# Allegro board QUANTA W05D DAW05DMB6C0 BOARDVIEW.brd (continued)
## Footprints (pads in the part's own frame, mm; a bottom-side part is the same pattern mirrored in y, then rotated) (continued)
BSH-030-01-L-D-A-TR-60P-LDH
  round 1.016 hole 1.016 unplated: (-10.063,-2.666) (10.063,-2.666)
  rect 0.279x2.261 smd: 1(-7.25,-2.864) 2(-6.75,-2.864) 3(-6.25,-2.864) 4(-5.75,-2.864) 5(-5.25,-2.864) 6(-4.75,-2.864) 7(-4.25,-2.864) 8(-3.75,-2.864) 9(-3.25,-2.864) 10(-2.75,-2.864) 11(-2.25,-2.864) 12(-1.75,-2.864) 13(-1.25,-2.864) 14(-0.75,-2.864) 15(-0.25,-2.864) 16(0.25,-2.864) 17(0.75,-2.864) 18(1.25,-2.864) 19(1.75,-2.864) 20(2.25,-2.864) 21(2.75,-2.864) 22(3.25,-2.864) 23(3.75,-2.864) 24(4.25,-2.864) 25(4.75,-2.864) 26(5.25,-2.864) 27(5.75,-2.864) 28(6.25,-2.864) 29(6.75,-2.864) 30(7.25,-2.864) 31(7.25,2.864) 32(6.75,2.864) 33(6.25,2.864) 34(5.75,2.864) 35(5.25,2.864) 36(4.75,2.864) 37(4.25,2.864) 38(3.75,2.864) 39(3.25,2.864) 40(2.75,2.864) 41(2.25,2.864) 42(1.75,2.864) 43(1.25,2.864) 44(0.75,2.864) 45(0.25,2.864) 46(-0.25,2.864) 47(-0.75,2.864) 48(-1.25,2.864) 49(-1.75,2.864) 50(-2.25,2.864) 51(-2.75,2.864) 52(-3.25,2.864) 53(-3.75,2.864) 54(-4.25,2.864) 55(-4.75,2.864) 56(-5.25,2.864) 57(-5.75,2.864) 58(-6.25,2.864) 59(-6.75,2.864) 60(-7.25,2.864)
CC0201_S
  rect 0.254x0.356 smd: 1(0.24,0) 2(-0.24,0)
CC0402
  custom 0.12x0.12 smd: 1(0.39,0) 2(-0.39,0)
CC0603
  rect 0.813x0.711 smd: 1(0.737,0) 2(-0.737,0)
CC0805
  rect 0.94x1.346 smd: 1(0.895,0) 2(-0.895,0)
CC3528
  rect 2.032x2.413 smd: 1(1.6,0) 2(-1.6,0)
CC7343-2_15H
  rect 2.057x2.896 smd: 1(-3.075,0) 2(3.075,0)
CHOKE-ETQP4LR36AFM
  rect 2.794x2.591 smd: 1(-3.2,0) 2(3.2,0)
CHOKE-MPL73-1R5
  rect 1.676x3.404 smd: 1(-2.843,0) 2(2.843,0)
CHOKE-WCM2012-4P
  rect 0.889x0.406 smd: 1(-0.85,0.4) 2(0.85,0.4) 3(0.85,-0.4) 4(-0.85,-0.4)
D-DO-214AC
  rect 1.88x2.032 smd: 1(-2.1,0) 2(2.1,0)
D-SOT523_213-1_6-1
  rect 0.406x0.508 smd: 1(0.5,-0.65) 2(-0.5,-0.65) 3(0,0.65)
DDR-DDRRK-20401-TP4B-204P-RUV
  round 1.092 hole 1.092 unplated: (-33.4,0)
  round 1.6 hole 1.6 unplated: (33.4,0)
  rect 0.356x2.007 smd: 1(31.65,4.1) 2(31.35,-4.1) 3(31.05,4.1) 4(30.75,-4.1) 5(30.45,4.1) 6(30.15,-4.1) 7(29.85,4.1) 8(29.55,-4.1) 9(29.25,4.1) 10(28.95,-4.1) 11(28.65,4.1) 12(28.35,-4.1) 13(28.05,4.1) 14(27.75,-4.1) 15(27.45,4.1) 16(27.15,-4.1) 17(26.85,4.1) 18(26.55,-4.1) 19(26.25,4.1) 20(25.95,-4.1) 21(25.65,4.1) 22(25.35,-4.1) 23(25.05,4.1) 24(24.75,-4.1) 25(24.45,4.1) 26(24.15,-4.1) 27(23.85,4.1) 28(23.55,-4.1) 29(23.25,4.1) 30(22.95,-4.1) 31(22.65,4.1) 32(22.35,-4.1) 33(22.05,4.1) 34(21.75,-4.1) 35(21.45,4.1) 36(21.15,-4.1) 37(20.85,4.1) 38(20.55,-4.1) 39(20.25,4.1) 40(19.95,-4.1) 41(19.65,4.1) 42(19.35,-4.1) 43(19.05,4.1) 44(18.75,-4.1) 45(18.45,4.1) 46(18.15,-4.1) 47(17.85,4.1) 48(17.55,-4.1) 49(17.25,4.1) 50(16.95,-4.1) 51(16.65,4.1) 52(16.35,-4.1) 53(16.05,4.1) 54(15.75,-4.1) 55(15.45,4.1) 56(15.15,-4.1) 57(14.85,4.1) 58(14.55,-4.1) 59(14.25,4.1) 60(13.95,-4.1) 61(13.65,4.1) 62(13.35,-4.1) 63(13.05,4.1) 64(12.75,-4.1) 65(12.45,4.1) 66(12.15,-4.1) 67(11.85,4.1) 68(11.55,-4.1) 69(11.25,4.1) 70(10.95,-4.1) 71(10.65,4.1) 72(10.35,-4.1) 73(7.65,4.1) 74(7.35,-4.1) 75(7.05,4.1) 76(6.75,-4.1) 77(6.45,4.1) 78(6.15,-4.1) 79(5.85,4.1) 80(5.55,-4.1) 81(5.25,4.1) 82(4.95,-4.1) 83(4.65,4.1) 84(4.35,-4.1) 85(4.05,4.1) 86(3.75,-4.1) 87(3.45,4.1) 88(3.15,-4.1) 89(2.85,4.1) 90(2.55,-4.1) 91(2.25,4.1) 92(1.95,-4.1) 93(1.65,4.1) 94(1.35,-4.1) 95(1.05,4.1) 96(0.75,-4.1) 97(0.45,4.1) 98(0.15,-4.1) 99(-0.15,4.1) 100(-0.45,-4.1) 101(-0.75,4.1) 102(-1.05,-4.1) 103(-1.35,4.1) 104(-1.65,-4.1) 105(-1.95,4.1) 106(-2.25,-4.1) 107(-2.55,4.1) 108(-2.85,-4.1) 109(-3.15,4.1) 110(-3.45,-4.1) 111(-3.75,4.1) 112(-4.05,-4.1) 113(-4.35,4.1) 114(-4.65,-4.1) 115(-4.95,4.1) 116(-5.25,-4.1) 117(-5.55,4.1) 118(-5.85,-4.1) 119(-6.15,4.1) 120(-6.45,-4.1) 121(-6.75,4.1) 122(-7.05,-4.1) 123(-7.35,4.1) 124(-7.65,-4.1) 125(-7.95,4.1) 126(-8.25,-4.1) 127(-8.55,4.1) 128(-8.85,-4.1) 129(-9.15,4.1) 130(-9.45,-4.1) 131(-9.75,4.1) 132(-10.05,-4.1) 133(-10.35,4.1) 134(-10.65,-4.1) 135(-10.95,4.1) 136(-11.25,-4.1) 137(-11.55,4.1) 138(-11.85,-4.1) 139(-12.15,4.1) 140(-12.45,-4.1) 141(-12.75,4.1) 142(-13.05,-4.1) 143(-13.35,4.1) 144(-13.65,-4.1) 145(-13.95,4.1) 146(-14.25,-4.1) 147(-14.55,4.1) 148(-14.85,-4.1) 149(-15.15,4.1) 150(-15.45,-4.1) 151(-15.75,4.1) 152(-16.05,-4.1) 153(-16.35,4.1) 154(-16.65,-4.1) 155(-16.95,4.1) 156(-17.25,-4.1) 157(-17.55,4.1) 158(-17.85,-4.1) 159(-18.15,4.1) 160(-18.45,-4.1) 161(-18.75,4.1) 162(-19.05,-4.1) 163(-19.35,4.1) 164(-19.65,-4.1) 165(-19.95,4.1) 166(-20.25,-4.1) 167(-20.55,4.1) 168(-20.85,-4.1) 169(-21.15,4.1) 170(-21.45,-4.1) 171(-21.75,4.1) 172(-22.05,-4.1) 173(-22.35,4.1) 174(-22.65,-4.1) 175(-22.95,4.1) 176(-23.25,-4.1) 177(-23.55,4.1) 178(-23.85,-4.1) 179(-24.15,4.1) 180(-24.45,-4.1) 181(-24.75,4.1) 182(-25.05,-4.1) 183(-25.35,4.1) 184(-25.65,-4.1) 185(-25.95,4.1) 186(-26.25,-4.1) 187(-26.55,4.1) 188(-26.85,-4.1) 189(-27.15,4.1) 190(-27.45,-4.1) 191(-27.75,4.1) 192(-28.05,-4.1) 193(-28.35,4.1) 194(-28.65,-4.1) 195(-28.95,4.1) 196(-29.25,-4.1) 197(-29.55,4.1) 198(-29.85,-4.1) 199(-30.15,4.1) 200(-30.45,-4.1) 201(-30.75,4.1) 202(-31.05,-4.1) 203(-31.35,4.1) 204(-31.65,-4.1)
  rect 4.496x4.597 smd: 207(32.55,12) 208(-32.55,12)
DSM
  rect 0.508x1.016 smd: 1(0,-1.3) 2(0,1.321)
F3_2X1_65-2_8
  rect 0.991x1.803 smd: 1(-1.4,0) 2(1.4,0)
FH35C-31S-0_3SHW-31P-LDH
  rect 0.305x0.787 smd: 1(-4.5,-1.475) 2(-3.9,-1.475) 3(-3.3,-1.475) 4(-2.7,-1.475) 5(-2.1,-1.475) 6(-1.5,-1.475) 7(-0.9,-1.475) 8(-0.3,-1.475) 9(0.3,-1.475) 10(0.9,-1.475) 11(1.5,-1.475) 12(2.1,-1.475) 13(2.7,-1.475) 14(3.3,-1.475) 15(3.9,-1.475) 16(4.5,-1.475)
  rect 0.305x0.66 smd: 17(4.2,1.4) 18(3.6,1.4) 19(3,1.4) 20(2.4,1.4) 21(1.8,1.4) 22(1.2,1.4) 23(0.6,1.4) 24(0,1.4) 25(-0.6,1.4) 26(-1.2,1.4) 27(-1.8,1.4) 28(-2.4,1.4) 29(-3,1.4) 30(-3.6,1.4) 31(-4.2,1.4)
  rect 0.406x0.94 smd: 32(-5.2,-1.2) 33(5.2,-1.2)
GS12407-11141-9H-40P-R
  rect 0.254x1.295 smd: 1(9.75,1.995) 2(9.25,1.995) 3(8.75,1.995) 4(8.25,1.995) 5(7.75,1.995) 6(7.25,1.995) 7(6.75,1.995) 8(6.25,1.995) 9(5.75,1.995) 10(5.25,1.995) 11(4.75,1.995) 12(4.25,1.995) 13(3.75,1.995) 14(3.25,1.995) 15(2.75,1.995) 16(2.25,1.995) 17(1.75,1.995) 18(1.25,1.995) 19(0.75,1.995) 20(0.25,1.995) 21(-0.25,1.995) 22(-0.75,1.995) 23(-1.25,1.995) 24(-1.75,1.995) 25(-2.25,1.995) 26(-2.75,1.995) 27(-3.25,1.995) 28(-3.75,1.995) 29(-4.25,1.995) 30(-4.75,1.995) 31(-5.25,1.995) 32(-5.75,1.995) 33(-6.25,1.995) 34(-6.75,1.995) 35(-7.25,1.995) 36(-7.75,1.995) 37(-8.25,1.995) 38(-8.75,1.995) 39(-9.25,1.995) 40(-9.75,1.995)
  rect 2.261x1.295 smd: 41(8.9,-1.905) 42(0,-1.905) 43(-8.9,-1.905)
  rect 1.194x3.2 smd: 44(12.15,0) 45(-12.15,0)
H-C91D91N
  round 2.311 hole 2.311 unplated: (0,0)
H-TC236IC142BC142D142P2
  round 3.607 hole 3.607: 1(0,0)
H-TE315X354BC138D138P2
  round 3.505 hole 3.505: 1(0,0)
H-TE354X299BC91D91P2
  round 2.311 hole 2.311: 1(0,0)
H-TE354X339BC91D91P2
  round 2.311 hole 2.311: 1(0,0)
H-TE354X339BC138D138P2
  round 3.505 hole 3.505: 1(0,0)
H-TE354X366BC138D138P2
  round 3.505 hole 3.505: 1(0,0)
H-TE413X295BC142D142P2
  round 3.607 hole 3.607: 1(0,0)
H-TE473X378BC138D138P2
  round 3.505 hole 3.505: 1(0,0)
L3_2X2_5-1_55
  rect 1.245x2.007 smd: 1(-1.275,0) 2(1.275,0)
LGA14-5X3-8
  rect 0.61x1.397 smd: 1(2,1.3) 2(1.2,1.3) 3(0.4,1.3) 4(-0.4,1.3) 5(-1.2,1.3) 6(-2,1.3) 8(-2,-1.3) 9(-1.2,-1.3) 10(-0.4,-1.3) 11(0.4,-1.3) 12(1.2,-1.3) 13(2,-1.3)
  rect 1.702x0.635 smd: 7(-2.15,0) 14(2.15,0)
LGA16-4X4-65
  rect 0.991x0.381 smd: 1(-2,0.975) 2(-2,0.325) 3(-2,-0.325) 4(-2,-0.975) 9(2,-0.975) 10(2,-0.325) 11(2,0.325) 12(2,0.975)
  rect 0.381x0.991 smd: 5(-0.975,-2) 6(-0.325,-2) 7(0.325,-2) 8(0.975,-2) 13(0.975,2) 14(0.325,2) 15(-0.325,2) 16(-0.975,2)
LQFP64-12X12-5-STM32F405RGT6TR
  rect 1.194x0.305 smd: 1(-5.75,3.75) 2(-5.75,3.25) 3(-5.75,2.75) 4(-5.75,2.25) 5(-5.75,1.75) 6(-5.75,1.25) 7(-5.75,0.75) 8(-5.75,0.25) 9(-5.75,-0.25) 10(-5.75,-0.75) 11(-5.75,-1.25) 12(-5.75,-1.75) 13(-5.75,-2.25) 14(-5.75,-2.75) 15(-5.75,-3.25) 16(-5.75,-3.75) 33(5.75,-3.75) 34(5.75,-3.25) 35(5.75,-2.75) 36(5.75,-2.25) 37(5.75,-1.75) 38(5.75,-1.25) 39(5.75,-0.75) 40(5.75,-0.25) 41(5.75,0.25) 42(5.75,0.75) 43(5.75,1.25) 44(5.75,1.75) 45(5.75,2.25) 46(5.75,2.75) 47(5.75,3.25) 48(5.75,3.75)
  rect 0.305x1.194 smd: 17(-3.75,-5.75) 18(-3.25,-5.75) 19(-2.75,-5.75) 20(-2.25,-5.75) 21(-1.75,-5.75) 22(-1.25,-5.75) 23(-0.75,-5.75) 24(-0.25,-5.75) 25(0.25,-5.75) 26(0.75,-5.75) 27(1.25,-5.75) 28(1.75,-5.75) 29(2.25,-5.75) 30(2.75,-5.75) 31(3.25,-5.75) 32(3.75,-5.75) 49(3.75,5.75) 50(3.25,5.75) 51(2.75,5.75) 52(2.25,5.75) 53(1.75,5.75) 54(1.25,5.75) 55(0.75,5.75) 56(0.25,5.75) 57(-0.25,5.75) 58(-0.75,5.75) 59(-1.25,5.75) 60(-1.75,5.75) 61(-2.25,5.75) 62(-2.75,5.75) 63(-3.25,5.75) 64(-3.75,5.75)
LQFP128-16X16-4
  rect 0.203x1.499 smd: 1(-6.2,-7.85) 2(-5.8,-7.85) 3(-5.4,-7.85) 4(-5,-7.85) 5(-4.6,-7.85) 6(-4.2,-7.85) 7(-3.8,-7.85) 8(-3.4,-7.85) 9(-3,-7.85) 10(-2.6,-7.85) 11(-2.2,-7.85) 12(-1.8,-7.85) 13(-1.4,-7.85) 14(-1,-7.85) 15(-0.6,-7.85) 16(-0.2,-7.85) 17(0.2,-7.85) 18(0.6,-7.85) 19(1,-7.85) 20(1.4,-7.85) 21(1.8,-7.85) 22(2.2,-7.85) 23(2.6,-7.85) 24(3,-7.85) 25(3.4,-7.85) 26(3.8,-7.85) 27(4.2,-7.85) 28(4.6,-7.85) 29(5,-7.85) 30(5.4,-7.85) 31(5.8,-7.85) 32(6.2,-7.85) 65(6.2,7.85) 66(5.8,7.85) 67(5.4,7.85) 68(5,7.85) 69(4.6,7.85) 70(4.2,7.85) 71(3.8,7.85) 72(3.4,7.85) 73(3,7.85) 74(2.6,7.85) 75(2.2,7.85) 76(1.8,7.85) 77(1.4,7.85) 78(1,7.85) 79(0.6,7.85) 80(0.2,7.85) 81(-0.2,7.85) 82(-0.6,7.85) 83(-1,7.85) 84(-1.4,7.85) 85(-1.8,7.85) 86(-2.2,7.85) 87(-2.6,7.85) 88(-3,7.85) 89(-3.4,7.85) 90(-3.8,7.85) 91(-4.2,7.85) 92(-4.6,7.85) 93(-5,7.85) 94(-5.4,7.85) 95(-5.8,7.85) 96(-6.2,7.85)
  rect 1.499x0.203 smd: 33(7.85,-6.2) 34(7.85,-5.8) 35(7.85,-5.4) 36(7.85,-5) 37(7.85,-4.6) 38(7.85,-4.2) 39(7.85,-3.8) 40(7.85,-3.4) 41(7.85,-3) 42(7.85,-2.6) 43(7.85,-2.2) 44(7.85,-1.8) 45(7.85,-1.4) 46(7.85,-1) 47(7.85,-0.6) 48(7.85,-0.2) 49(7.85,0.2) 50(7.85,0.6) 51(7.85,1) 52(7.85,1.4) 53(7.85,1.8) 54(7.85,2.2) 55(7.85,2.6) 56(7.85,3) 57(7.85,3.4) 58(7.85,3.8) 59(7.85,4.2) 60(7.85,4.6) 61(7.85,5) 62(7.85,5.4) 63(7.85,5.8) 64(7.85,6.2) 97(-7.85,6.2) 98(-7.85,5.8) 99(-7.85,5.4) 100(-7.85,5) 101(-7.85,4.6) 102(-7.85,4.2) 103(-7.85,3.8) 104(-7.85,3.4) 105(-7.85,3) 106(-7.85,2.6) 107(-7.85,2.2) 108(-7.85,1.8) 109(-7.85,1.4) 110(-7.85,1) 111(-7.85,0.6) 112(-7.85,0.2) 113(-7.85,-0.2) 114(-7.85,-0.6) 115(-7.85,-1) 116(-7.85,-1.4) 117(-7.85,-1.8) 118(-7.85,-2.2) 119(-7.85,-2.6) 120(-7.85,-3) 121(-7.85,-3.4) 122(-7.85,-3.8) 123(-7.85,-4.2) 124(-7.85,-4.6) 125(-7.85,-5) 126(-7.85,-5.4) 127(-7.85,-5.8) 128(-7.85,-6.2)
MINIPCI-MPCET-SSC10-TS10-52P
  rect 0.61x1.295 smd: 1(11.8,8.15) 3(11,8.15) 5(10.2,8.15) 7(9.4,8.15) 9(8.6,8.15) 11(7.8,8.15) 13(7,8.15) 15(6.2,8.15) 17(2.2,8.15) 19(1.4,8.15) 21(0.6,8.15) 23(-0.2,8.15) 25(-1,8.15) 27(-1.8,8.15) 29(-2.6,8.15) 31(-3.4,8.15) 33(-4.2,8.15) 35(-5,8.15) 37(-5.8,8.15) 39(-6.6,8.15) 41(-7.4,8.15) 43(-8.2,8.15) 45(-9,8.15) 47(-9.8,8.15) 49(-10.6,8.15) 51(-11.4,8.15)
  oval 0.61x0.889 hole 0.381x0.61: 2(11.4,6.65) 4(10.6,6.65) 6(9.8,6.65) 8(9,6.65) 10(8.2,6.65) 12(7.4,6.65) 14(6.6,6.65) 16(5.8,6.65) 18(1.8,6.65) 20(1,6.65) 22(0.2,6.65) 24(-0.6,6.65) 26(-1.4,6.65) 28(-2.2,6.65) 30(-3,6.65) 32(-3.8,6.65) 34(-4.6,6.65) 36(-5.4,6.65) 38(-6.2,6.65) 40(-7,6.65) 42(-7.8,6.65) 44(-8.6,6.65) 46(-9.4,6.65) 48(-10.2,6.65) 50(-11,6.65) 52(-11.8,6.65)
  oval 0.787x2.388 hole 0.406x2.007: 53(14.35,0) 54(-14.35,0)
ML1220-SMT
  round 0.711 hole 0.711 unplated: (0,-3.988)
  round 1.092 hole 1.092 unplated: (0,3.988)
  rect 2.997x1.499 smd: 1(-7.391,0) 2(7.391,0)
MSOP8-4_9-65
  rect 0.406x1.448 smd: 1(-0.975,-2.325) 2(-0.325,-2.325) 3(0.325,-2.325) 4(0.975,-2.325) 5(0.975,2.325) 6(0.325,2.325) 7(-0.325,2.325) 8(-0.975,2.325)
PG-TSDSON-8-8P-R
  rect 0.33x0.787 smd: 1(0.975,1.5) 2(0.325,1.5) 3(-0.325,1.5) 4(-0.975,1.5)
  custom 0.573x0.573 smd: 5(0,-0.72)
  rect 0.33x0.66 smd: 6(-0.325,-1.575) 7(0.325,-1.575) 8(0.975,-1.575)
POWER-5X6-1_27-7P
  rect 0.66x0.635 smd: 1(-1.905,-2.835) 5(1.905,2.835) 6(0.635,2.835) 7(-0.635,2.835) 8(-1.905,2.835)
  custom 0.485x0.485 smd: 2(0.115,-2.18)
  rect 3.988x2.159 smd: 9(0,0.525)
PVQFN20-3_5X3_5-5-25P
  rect 0.279x0.838 smd: 1(-1,-1.725) 2(-0.5,-1.725) 3(0,-1.725) 4(0.5,-1.725) 5(1,-1.725) 11(1,1.725) 12(0.5,1.725) 13(0,1.725) 14(-0.5,1.725) 15(-1,1.725)
  rect 0.838x0.279 smd: 6(1.725,-1) 7(1.725,-0.5) 8(1.725,0) 9(1.725,0.5) 10(1.725,1) 16(-1.725,1) 17(-1.725,0.5) 18(-1.725,0) 19(-1.725,-0.5) 20(-1.725,-1)
  rect 2.057x2.057 smd: 21(0,0)
  round 0.61 hole 0.305: 22(-0.5,-0.5) 23(0.5,-0.5) 24(0.5,0.5) 25(-0.5,0.5)
PVQFN24-4X4-5-34P
  rect 0.279x0.838 smd: 1(1.25,1.975) 2(0.75,1.975) 3(0.25,1.975) 4(-0.25,1.975) 5(-0.75,1.975) 6(-1.25,1.975) 13(-1.25,-1.975) 14(-0.75,-1.975) 15(-0.25,-1.975) 16(0.25,-1.975) 17(0.75,-1.975) 18(1.25,-1.975)
  rect 0.838x0.279 smd: 7(-1.975,1.25) 8(-1.975,0.75) 9(-1.975,0.25) 10(-1.975,-0.25) 11(-1.975,-0.75) 12(-1.975,-1.25) 19(1.975,-1.25) 20(1.975,-0.75) 21(1.975,-0.25) 22(1.975,0.25) 23(1.975,0.75) 24(1.975,1.25)
  rect 2.438x2.438 smd: 25(0,0)
  round 0.61 hole 0.305: 26(-0.75,0.75) 27(0,0.75) 28(0.75,0.75) 29(-0.75,0) 30(0,0) 31(0.75,0) 32(-0.75,-0.75) 33(0,-0.75) 34(0.75,-0.75)
PWQFN20-4X4-5-30P
  rect 0.279x0.838 smd: 1(1,1.975) 2(0.5,1.975) 3(0,1.975) 4(-0.5,1.975) 5(-1,1.975) 11(-1,-1.975) 12(-0.5,-1.975) 13(0,-1.975) 14(0.5,-1.975) 15(1,-1.975)
  rect 0.838x0.279 smd: 6(-1.975,1) 7(-1.975,0.5) 8(-1.975,0) 9(-1.975,-0.5) 10(-1.975,-1) 16(1.975,-1) 17(1.975,-0.5) 18(1.975,0) 19(1.975,0.5) 20(1.975,1)
  rect 2.692x2.692 smd: 21(0,0)
  round 0.61 hole 0.305: 22(-0.9,0.9) 23(0,0.9) 24(0.9,0.9) 25(-0.9,0) 26(0,0) 27(0.9,0) 28(-0.9,-0.9) 29(0,-0.9) 30(0.9,-0.9)
QFN14-3X3-4-16P
  rect 1.092x0.203 smd: 1(-1.25,0.525) 2(-1.25,-0.175) 8(1.25,-0.525) 9(1.25,0.175)
  rect 0.203x0.711 smd: 3(-0.8,-1.45) 4(-0.4,-1.45) 5(0,-1.45) 6(0.4,-1.45) 7(0.8,-1.45) 10(0.8,1.45) 11(0.4,1.45) 12(0,1.45) 13(-0.4,1.45) 14(-0.8,1.45)
  rect 0.66x0.203 smd: 15(0,0.165) 16(0,-0.435)
QFN20-4X4-5-21P-ADG786
  rect 0.279x1.194 smd: 1(-1,-2) 2(-0.5,-2) 3(0,-2) 4(0.5,-2) 5(1,-2) 11(1,2) 12(0.5,2) 13(0,2) 14(-0.5,2) 15(-1,2)
  rect 1.194x0.279 smd: 6(2,-1) 7(2,-0.5) 8(2,0) 9(2,0.5) 10(2,1) 16(-2,1) 17(-2,0.5) 18(-2,0) 19(-2,-0.5) 20(-2,-1)
  rect 2.108x2.108 smd: 21(0,0)
QFN23-4X4-5
  rect 0.457x0.254 smd: 1(-1.825,1.25) 2(-1.825,0.75) 3(-1.825,0.25) 4(-1.825,-0.25) 5(-1.825,-0.75) 6(-1.825,-1.25) 12(1.825,-1.25) 13(1.825,-0.75) 14(1.825,-0.25) 15(1.825,0.25) 16(1.825,0.75) 17(1.825,1.25)
  rect 0.254x0.457 smd: 7(-1.25,-1.825) 8(-0.75,-1.825) 10(0.75,-1.825) 18(1.25,1.825) 19(0.75,1.825) 20(0.25,1.825) 21(-0.25,1.825) 22(-0.75,1.825) 23(-1.25,1.825)
  custom 0.335x0.335 smd: 9(-0.67,-0.335)
  custom 0.249x0.249 smd: 11(0.867,-0.335)
QFN28-4X4-4-29P-NCP81101MNTWG
  rect 0.965x0.203 smd: 1(-2.03,1.2) 2(-2.03,0.8) 3(-2.03,0.4) 4(-2.03,0) 5(-2.03,-0.4) 6(-2.03,-0.8) 7(-2.03,-1.2) 15(2.03,-1.2) 16(2.03,-0.8) 17(2.03,-0.4) 18(2.03,0) 19(2.03,0.4) 20(2.03,0.8) 21(2.03,1.2)
  rect 0.203x0.965 smd: 8(-1.2,-2.03) 9(-0.8,-2.03) 10(-0.4,-2.03) 11(0,-2.03) 12(0.4,-2.03) 13(0.8,-2.03) 14(1.2,-2.03) 22(1.2,2.03) 23(0.8,2.03) 24(0.4,2.03) 25(0,2.03) 26(-0.4,2.03) 27(-0.8,2.03) 28(-1.2,2.03)
  rect 2.718x2.718 smd: 29(0,0)
QFN40-5X5-4-41P-92HD99
  rect 0.203x0.991 smd: 1(-1.8,-2.6) 2(-1.4,-2.6) 3(-1,-2.6) 4(-0.6,-2.6) 5(-0.2,-2.6) 6(0.2,-2.6) 7(0.6,-2.6) 8(1,-2.6) 9(1.4,-2.6) 10(1.8,-2.6) 21(1.8,2.6) 22(1.4,2.6) 23(1,2.6) 24(0.6,2.6) 25(0.2,2.6) 26(-0.2,2.6) 27(-0.6,2.6) 28(-1,2.6) 29(-1.4,2.6) 30(-1.8,2.6)
  rect 0.991x0.203 smd: 11(2.6,-1.8) 12(2.6,-1.4) 13(2.6,-1) 14(2.6,-0.6) 15(2.6,-0.2) 16(2.6,0.2) 17(2.6,0.6) 18(2.6,1) 19(2.6,1.4) 20(2.6,1.8) 31(-2.6,1.8) 32(-2.6,1.4) 33(-2.6,1) 34(-2.6,0.6) 35(-2.6,0.2) 36(-2.6,-0.2) 37(-2.6,-0.6) 38(-2.6,-1) 39(-2.6,-1.4) 40(-2.6,-1.8)
  rect 3.708x3.708 smd: 41(0,0)
RC0201_S
  rect 0.254x0.356 smd: 1(0.24,0) 2(-0.24,0)
RC0402
  custom 0.12x0.12 smd: 1(0.39,0) 2(-0.39,0)
RC0603
  rect 0.813x0.711 smd: 1(0.737,0) 2(-0.737,0)
RC0805
  rect 0.94x1.346 smd: 1(0.895,0) 2(-0.895,0)
SC70-2_1-65-6P
  rect 1.27x0.279 smd: 1(1.02,-0.65) 2(1.02,0) 3(1.02,0.65) 4(-1.02,0.65) 5(-1.02,0) 6(-1.02,-0.65)
SHORT0201
  rect 0.343x0.381 smd: 1(-0.225,0) 2(0.225,0)
SHORT0402
  rect 0.648x0.5 smd: 1(-0.39,0) 2(0.39,0)
SHORT0603
  rect 1.219x0.711 smd: 1(0.737,0) 2(-0.737,0)
SHORT0805
  rect 1.422x1.346 smd: 1(0.895,0) 2(-0.895,0)
SHORT-SOLDERJUMPER-3
  custom 0.508x0.508 smd: 1(-1.016,0)
  custom 0.381x0.381 smd: 2(1.016,0)
SO-8FL-5P
  rect 0.762x0.991 smd: 1(1.905,3.73) 2(0.635,3.73) 3(-0.635,3.73) 4(-1.905,3.73)
  custom 1.132x1.132 smd: 5(0,0)
SOIC8-8-1_27
  rect 0.533x1.6 smd: 1(1.905,3.8) 2(0.635,3.8) 3(-0.635,3.8) 4(-1.905,3.8) 5(-1.905,-3.8) 6(-0.635,-3.8) 7(0.635,-3.8) 8(1.905,-3.8)
SOT23-5
  rect 0.711x1.016 smd: 1(-0.95,-1.2) 2(0,-1.2) 3(0.95,-1.2) 4(0.95,1.2) 5(-0.95,1.2)
SOT23_213-3_3-2
  rect 1.016x1.27 smd: 1(1.016,-1.016) 2(-1.016,-1.016) 3(0,1.016)
SOT353-1-2_125-65-5P
  rect 0.279x1.245 smd: 1(-0.65,-1.045) 2(0,-1.045) 3(0.65,-1.045) 4(0.65,1.045) 5(-0.65,1.045)
SOT363-2_1-65-6P
  rect 0.889x0.356 smd: 1(0.8,-0.65) 2(0.8,0) 3(0.8,0.65) 4(-0.8,0.65) 5(-0.8,0) 6(-0.8,-0.65)
SOT523_213-1_6-1-3P
  rect 0.279x1.118 smd: 1(0.5,-0.84) 2(-0.5,-0.84) 3(0,0.84)
SSOP5-P-A-TOSHIBA-B
  rect 0.305x1.067 smd: 1(0.65,0.85) 2(0,0.85) 3(-0.65,0.85) 4(-0.65,-0.85) 5(0.65,-0.85)
TO252_134-9_9-4_57-SMT
  rect 2.997x1.499 smd: 1(8.1,-2.286) 3(8.1,2.286)
  rect 5.613x6.248 smd: 4(0.6,0)
TP1250-P14_4
  round 0.305 smd: 1(0,0)
TP2050
  round 0.508 smd: 1(0,0)
TP2075
  round 0.508 smd: 1(0,0)
TP2650
  round 0.66 smd: 1(0,0)
TP2675
  round 0.66 smd: 1(0,0)
TQFN20-3X3-4-21P
  rect 0.711x0.203 smd: 1(-1.5,0.8) 2(-1.5,0.4) 3(-1.5,0) 4(-1.5,-0.4) 5(-1.5,-0.8) 11(1.5,-0.8) 12(1.5,-0.4) 13(1.5,0) 14(1.5,0.4) 15(1.5,0.8)
  rect 0.203x0.711 smd: 6(-0.8,-1.5) 7(-0.4,-1.5) 8(0,-1.5) 9(0.4,-1.5) 10(0.8,-1.5) 16(0.8,1.5) 17(0.4,1.5) 18(0,1.5) 19(-0.4,1.5) 20(-0.8,1.5)
  rect 1.499x1.499 smd: 21(0,0)
TSOP6-2_8-95
  rect 0.635x0.787 smd: 1(-0.95,-1.2) 2(0,-1.2) 3(0.95,-1.2) 4(0.95,1.2) 5(0,1.2) 6(-0.95,1.2)
TSSOP28-6_4-65
  rect 0.279x1.499 smd: 1(-4.225,-3.038) 2(-3.575,-3.038) 3(-2.925,-3.038) 4(-2.275,-3.038) 5(-1.625,-3.038) 6(-0.975,-3.038) 7(-0.325,-3.038) 8(0.325,-3.038) 9(0.975,-3.038) 10(1.625,-3.038) 11(2.275,-3.038) 12(2.925,-3.038) 13(3.575,-3.038) 14(4.225,-3.038) 15(4.225,3.038) 16(3.575,3.038) 17(2.925,3.038) 18(2.275,3.038) 19(1.625,3.038) 20(0.975,3.038) 21(0.325,3.038) 22(-0.325,3.038) 23(-0.975,3.038) 24(-1.625,3.038) 25(-2.275,3.038) 26(-2.925,3.038) 27(-3.575,3.038) 28(-4.225,3.038)
UMT_213-3-1_3
  rect 1.016x0.762 smd: 1(0.991,0.66) 2(0.991,-0.66) 3(-0.991,0)
unnamed#2
  round 1.016 smd: 1(0,0)
VQFN14-3_5X3_5-5-15P
  rect 0.838x0.279 smd: 1(-1.725,-0.75) 7(1.725,-0.75) 8(1.725,0.75) 14(-1.725,0.75)
  rect 0.279x0.838 smd: 2(-1,-1.725) 3(-0.5,-1.725) 4(0,-1.725) 5(0.5,-1.725) 6(1,-1.725) 9(1,1.725) 10(0.5,1.725) 11(0,1.725) 12(-0.5,1.725) 13(-1,1.725)
  rect 2.057x2.057 smd: 15(0,0)
XTL-3_2X1_5-2_5-0_8H
  rect 0.991x1.803 smd: 1(-1.25,0) 2(1.25,0)
XTL-3_2X2_5-2_2X1_7-0_8H
  rect 1.397x1.194 smd: 1(-1.1,-0.85) 2(1.1,-0.85) 3(1.1,0.85) 4(-1.1,0.85)
XTL-3_2X2_5-2_2X1_8-4P
  rect 1.397x1.194 smd: 1(-1.1,-0.9) 2(1.1,-0.9) 3(1.1,0.9) 4(-1.1,0.9)

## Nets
51216VBST: PR125.2 PU8.15
51216VBST_S: PC143.1 PR125.1
51216VDDQSNS: PR126.1 PU8.9
81101VCC: PC61.2 PR66.1 PU3.28
81101VRMP: PC64.1 PR64.1 PU3.7
81101VSN: PC47.2 PR37.1 PU3.26
81101VSP: PC60.2 PR45.1 PU3.27
+0.75V_DDR_VTT: C308.1 C313.1 C324.1 C338.1 C339.1 JDIM1.203 JDIM1.204 PC141.1 PU8.1 PU8.3
+1.05V: C50.2 C120.1 C139.1 C162.1 C168.1 C175.1 C176.1 C250.1 C262.2 CN1.9 CN1.52 L6.2 L7.2 L11.2 PC90.1 PC105.1 PJP1.2 PL10.2 PQ5.5 PQ5.6 PQ5.7 PQ5.8 R46.2 R74.2 R75.2 R118.1 R328.1 R350.2 U20.AE8 U20.AE9 U20.AF9 U20.AF22 U20.AG8 U20.AG13 U20.AG14 U20.AG16 U20.AG17 U20.H11 U20.H15 U20.J11 U20.N8 U20.P9
+1.5V: C27.1 C73.1 C167.1 C352.1 C356.1 C359.1 CN5.6 CN5.28 CN5.48 CN14.6 CN14.28 CN14.48 L16.1 PC45.1 PC59.2 PL2.2 PR59.1 R260.2 R431.2 U20.J15
+1.05V_MODPHY: C58.2 C99.2 C100.2 L9.1 L10.1 PC92.1 PC107.1 PL10.1 PQ5.1 PQ5.2 PQ5.3 PR65.1 U20.K9 U20.L10 U20.M9
+1.05V_S2: PC62.1 PC63.1 PC69.1 PC70.1 PC94.1 PJP1.1 PL9.2 PR85.2
+1.05VS5: R329.1 R343.1 R347.1 R350.1 R351.1
+1.8VREF: PC139.1 PR124.1 PU8.6
+1.35VSUS: C299.1 C300.1 C301.1 C302.1 C303.1 C304.1 C305.1 C306.1 C310.1 C315.1 C316.1 C317.1 C318.1 C321.1 C322.1 C325.1 C326.1 C327.1 C328.1 C329.1 C330.1 C331.1 C332.1 C333.1 C334.1 C335.1 C336.1 JDIM1.75 JDIM1.76 JDIM1.81 JDIM1.82 JDIM1.87 JDIM1.88 JDIM1.93 JDIM1.94 JDIM1.99 JDIM1.100 JDIM1.105 JDIM1.106 JDIM1.111 JDIM1.112 JDIM1.117 JDIM1.118 JDIM1.123 JDIM1.124 PC147.1 PJP4.2 PU8.2 Q27.3 R384.1 R455.2 R466.1 U20.AH26 U20.AJ31 U20.AJ33 U20.AJ37 U20.AN33 U20.AP43 U20.AR48 U20.AY35 U20.AY40 U20.AY44 U20.AY50 U22.5
+1.35VSUS_S: PC146.1 PC148.1 PJP4.1 PL14.2 PR126.2
+3.3VS5_S: PC8.1 PC9.1 PC10.1 PC58.1 PC76.1 PC78.1 PJP2.1 PL5.2 PR78.2
+3V: C2.2 C3.2 C4.2 C13.2 C17.2 C38.2 C42.1 C67.2 C72.2 C83.1 C84.1 C94.2 C115.1 C177.2 C181.1 C242.1 C243.1 C277.2 C289.1 C291.2 C295.2 C297.1 C307.1 C314.1 C319.1 C320.1 C346.1 C347.1 C355.1 C357.1 C358.1 C360.1 C362.2 C364.2 C365.2 CN3.1 CN12.1 CN12.2 CN13.15 CN13.16 CN14.2 CN14.24 CN14.39 CN14.41 CN14.52 EC2.1 EC4.1 EC5.1 EC8.1 EC9.1 EC11.1 EC12.1 EC15.1 JDIM1.199 L14.2 L15.2 L17.1 L18.1 PC98.1 PC99.1 PQ10.1 PQ10.2 PQ10.3 PR61.2 PR77.2 Q21.2 Q21.5 Q22.2 Q22.5 R14.2 R18.2 R25.1 R38.1 R47.2 R51.2 R53.2 R56.1 R58.2 R59.1 R65.2 R77.2 R79.2 R86.2 R89.2 R98.1 R99.1 R105.1 R106.1 R113.2 R116.1 R119.1 R128.2 R132.1 R139.1 R151.1 R160.1 R161.1 R177.2 R184.1 R185.1 R187.2 R188.2 R189.2 R190.2 R191.2 R193.1 R194.2 R197.2 R198.2 R199.2 R201.1 R202.2 R203.2 R204.2 R208.2 R209.1 R214.2 R215.2 R216.2 R217.2 R218.2 R219.2 R248.2 R259.2 R269.1 R273.2 R285.2 R286.1 R287.2 R288.2 R290.1 R291.2 R293.2 R294.2 R299.1 R302.2 R304.2 R305.1 R308.2 R310.1 R312.1 R313.2 R314.2 R320.2 R324.2 R337.2 R338.2 R345.2 R346.2 R356.2 R430.2 R451.2 R457.2 R462.1 R469.2 RP1.5 RP1.10 RP2.5 RP2.10 RP3.5 RP3.10 U1.1 U1.14 U3.14 U5.1 U5.13 U5.19 U5.32 U5.48 U5.64 U8.4 U8.5 U10.6 U10.10 U10.16 U10.20 U13.1 U15.10 U15.19 U15.24 U20.K14 U20.K16 U20.T9 U20.U8 U20.V8 U20.W9 U21.1 U23.1 U23.4 U23.5 U23.15 U23.16
+3V_AVDD: C229.2 C231.1 C268.1 C269.1 L15.1 R317.1 R334.2 U14.5 U18.22
+3V_AVDD_2: C227.1 C232.1 L14.1 U18.30
+3V_DEEP_SUS: C109.2 C233.2 C241.2 C249.2 CN2.1 R140.1 R205.2 R264.1 R268.1 R271.2 R300.1 R315.1 R325.2 R326.2 R333.2 R348.2 R349.1 R352.2 R358.2 R363.2 R364.2 R369.1 R370.1 R372.2 R373.2 R374.2 R377.2 R378.1 R379.2 R381.2 R396.2 R400.2 R403.1 R404.2 R406.2 R407.2 R408.2 R412.1 R413.2 R422.2 R425.1 R426.2 R438.2 R448.2 U11.5 U17.1 U20.AA9 U20.AC9 U20.AE20 U20.AE21 U20.AH11
+3V_DVDD: C252.1 C253.1 L18.2 R237.2 U18.9
+3V_DVDD-IO: C236.1 L16.2 L17.2 U18.7
+3V_RTC: C9.1 C290.1 C292.1 C293.1 D1.3 R22.1 R23.1 R410.1 R415.2 R423.1 U20.AG10
+3V_RTC_0: CN4.1 Q1.1 R15.1
+3V_RTC_1: D1.1 R15.2
+3V_WLAN_P: C11.1 C68.1 C92.1 C150.1 C157.1 C366.1 CN5.2 CN5.24 CN5.39 CN5.41 CN5.52 Q7.3 Q12.2 Q13.2 R42.2 R48.1 R51.1 R57.2 R120.2
+3VLCD_CON: C75.1 C88.2 C104.2 C113.1 C122.2 CN7.11 CN7.12 L8.1
+3VPCU: C23.2 C30.1 C31.1 C32.1 C65.1 C69.1 C87.1 C125.1 C179.1 C184.1 C192.1 C195.1 C323.2 CN6.40 CN13.13 D1.2 D3.1 L1.2 PC84.2 PR72.2 PR119.1 PU4.6 R13.1 R16.1 R24.1 R27.1 R33.1 R37.1 R44.1 R50.2 R61.2 R84.1 R100.1 R104.1 R107.1 R125.1 R162.1 R178.1 R179.1 R186.1 R220.1 R221.1 R222.1 R223.1 R224.1 R225.1 R226.1 R477.1 R478.2 R479.1 R480.1 R482.1 R485.1 U4.6 U7.9 U7.22 U7.33 U7.96 U7.111 U7.125
+3VPCU_EC: C12.1 C18.1 L1.1 U7.67
+3VS5: C5.2 C34.1 C118.2 C180.2 C182.1 C244.2 C245.2 C287.1 CN2.7 PC112.2 PJP2.2 PQ10.5 PQ10.6 PQ10.7 PQ10.8 PR49.1 PR84.1 Q7.1 R122.1 R130.1 R133.1 R137.1 R147.1 R149.1 R163.1 R165.1 R192.1 R254.1 R271.1 R360.2 R368.2 R385.2 R389.2 R402.2 R405.2 R428.2 R445.2 U12.1 U12.13 U15.5 U16.5 U17.4 U17.5 U20.AH10
+3VSPI: C152.1 C153.2 R112.2 R140.2 R153.1 R179.2 U9.8
+5V: C44.1 C111.1 C126.2 C156.1 C196.1 C201.1 C207.1 C343.2 C344.1 CN6.8 CN6.9 FAN1.1 L13.2 PC125.1 PC126.1 PQ11.1 PQ11.2 PQ11.3 PR73.1 Q10.2 R41.1 R67.1 R246.1 R252.1 R475.2 R476.2 U6.1 U14.1
+5V_AMP: C217.2 C225.2 L13.1 R330.1 R335.2 U19.12 U19.20
+5V_PVDD: C199.1 C200.1 C216.1 C222.1 R246.2 U18.31 U18.38
+5VALW: PC24.2 PD2.1 PU4.11
+5VPCU: PD2.3 PR25.2 R19.2 R21.1 R471.1
+5VS5: PC17.2 PC18.2 PC123.2 PC142.1 PD2.2 PJP3.2 PQ11.5 PQ11.6 PQ11.7 PQ11.8 PR66.2 PU1.7 PU1.21 PU3.15 PU8.12 R464.1
+5VS5_S: PC95.1 PC106.1 PC108.1 PC109.1 PC110.1 PC111.1 PJP3.1 PL4.2 PR88.2 PU5.7
+12VALW: PC101.1 PU6.13
+V1.05A_AOSCSUS: C286.2 TP34.1 U20.AB8
+V1.05A_SUS_PCH: TP35.1 U20.AD8 U20.AD10
+V1.05A_USB2SUS: TP49.1 U20.AH13
+V1.05A_VCCUSB3SUS: TP18.1 U20.J13
+V1.05S_APLLOPI: C95.1 C124.1 C149.1 L7.1 U20.AA21 U20.W21
+V1.05S_ASATA3PLL: C93.2 C123.2 C135.2 L9.2 R155.1 R169.1 U20.B11
+V1.05S_AUSB3PLL: C116.2 C136.2 C169.2 L10.2 R164.1 R174.2 U20.B18
+V1.05S_AXCK_DCB: C70.1 C71.1 C82.1 L6.1 U20.J18 U20.K19
+V1.05S_AXCK_LCPLL: C117.1 C151.1 C170.1 L11.1 R180.1 U20.A20
+V1.05S_SSCF100: C85.2 R74.1 U20.J17
+V1.05S_SSCFF: C76.2 R75.1 U20.R21 U20.T21
+V1.05S_VCCST: C258.1 C259.1 PC100.2 PR75.1 PR89.1 PR90.1 PR97.1 R32.2 R55.1 R96.2 R114.2 R244.1 R253.1 R258.1 R266.2 R277.1 R328.2 R437.1 U20.AC22 U20.AE22 U20.AE23
+V3.3DX_1.5DX_ADO: C294.1 R430.1 R431.1 U20.AH14
+V3.3M_PSPI: C186.1 R187.1 R205.1 U20.Y8
+VCC_CORE: C20.1 C21.1 C35.1 C46.1 C47.1 C48.1 C49.1 C59.1 C60.1 C61.1 C62.1 C63.1 C77.1 C78.1 C79.1 C80.1 C81.1 C103.1 C105.1 C106.1 C107.1 C108.1 C127.1 C129.1 C130.1 C131.1 C132.1 C164.1 C165.1 C166.1 EC1.1 EC3.1 EC6.1 EC7.1 PC32.1 PC33.1 PC34.1 PC71.1 PC72.1 PC82.1 PC93.1 PC102.1 PL7.2 PR40.2 R243.2 U20.AB57 U20.AD57 U20.AG57 U20.C24 U20.C28 U20.C32 U20.C36 U20.C40 U20.C44 U20.C48 U20.C52 U20.C56 U20.E23 U20.E25 U20.E27 U20.E29 U20.E31 U20.E33 U20.E35 U20.E37 U20.E39 U20.E41 U20.E43 U20.E45 U20.E47 U20.E49 U20.E51 U20.E53 U20.E55 U20.E57 U20.F24 U20.F28 U20.F32 U20.F36 U20.F40 U20.F44 U20.F48 U20.F52 U20.F56 U20.F59 U20.G23 U20.G25 U20.G27 U20.G29 U20.G31 U20.G33 U20.G35 U20.G37 U20.G39 U20.G41 U20.G43 U20.G45 U20.G47 U20.G49 U20.G51 U20.G53 U20.G55 U20.G57 U20.H23 U20.J23 U20.K23 U20.K57 U20.L22 U20.M23 U20.M57 U20.P57 U20.U57 U20.W57
+VCC_TS: C41.2 C53.1 CN11.1 R59.2 U6.5
+VCCIO_OUT: C163.1 R82.2 R118.2 U20.A59
+VCCIOA_OUT: R181.1 U20.E20
+VCCRTCEXT: C285.1 U20.AE7
+VIN: C54.2 L5.2 PC1.1 PC2.1 PC3.1 PC4.1 PC7.1 PC35.1 PC36.1 PC37.1 PC38.2 PC39.1 PC46.1 PC81.1 PC151.1 PD1.1 PL1.2 PL3.2 PL6.2 PL8.1 PL15.2 PQ2.5 PQ2.6 PQ2.7 PQ2.8 PR24.1 PR70.1 PR116.2 PR117.2
+VIN_1.05V: PC15.1 PC16.1 PC19.2 PC20.2 PL1.1 PR6.1 PU1.8 PU1.9 PU1.22
+VIN_3VS5: PC48.1 PC49.1 PC51.2 PC52.2 PL3.1 PU4.1
+VIN_5VS5: PC54.2 PC55.2 PC56.1 PC57.1 PL6.1 PU5.1
+VIN_BLIGHT: C86.1 C110.2 C121.1 CN7.19 CN7.20 L5.1
+VIN_DDR: PC144.1 PC145.1 PC149.2 PC150.2 PL15.1 PQ15.5 PQ15.6 PQ15.7 PQ15.8
+VIN_VCC_CORE: PC65.1 PC66.1 PC67.1 PC74.1 PC86.2 PL8.2 PQ3.2 PR64.2
AGND: C206.1 C214.1 C215.1 C217.1 C221.1 C225.1 C229.1 C231.2 C234.1 C240.2 C246.1 C254.2 C257.1 C265.2 C266.2 C267.2 C268.2 C269.2 C271.2 C273.1 C361.1 CN8.28 CN8.29 CN8.30 CN8.31 Q23.1 R11.1 R340.2 U19.3 U19.9 U19.10 U19.13 U19.19 U19.21 U19.22 U19.23 U19.24 U19.25 U19.26 U19.27 U19.28 U19.29 U19.30
GND: C2.1 C3.1 C4.1 C8.2 C9.2 C11.2 C12.2 C13.1 C14.1 C15.2 C16.2 C17.1 C18.2 C19.2 C20.2 C21.2 C22.1 C23.1 C24.2 C25.1 C26.1 C27.2 C28.1 C29.2 C30.2 C31.2 C32.2 C33.1 C35.2 C36.1 C37.1 C38.1 C39.1 C40.1 C41.1 C42.2 C43.1 C44.2 C45.1 C46.2 C47.2 C48.2 C49.2 C50.1 C51.2 C53.2 C54.1 C55.2 C56.2 C58.1 C59.2 C60.2 C61.2 C62.2 C63.2 C65.2 C66.1 C67.1 C68.2 C69.2 C70.2 C71.2 C72.1 C73.2 C75.2 C76.1 C77.2 C78.2 C79.2 C80.2 C81.2 C82.2 C83.2 C84.2 C85.1 C86.2 C87.2 C88.1 C89.1 C92.2 C93.1 C94.1 C95.2 C98.2 C99.1 C100.1 C103.2 C104.1 C105.2 C106.2 C107.2 C108.2 C109.1 C110.1 C111.2 C112.2 C113.2 C115.2 C116.1 C117.2 C118.1 C119.2 C120.2 C121.2 C122.1 C123.1 C124.2 C125.2 C126.1 C127.2 C128.2 C129.2 C130.2 C131.2 C132.2 C133.2 C134.2 C135.1 C136.1 C137.2 C138.2 C139.2 C146.2 C147.1 C148.2 C149.2 C150.2 C151.2 C152.2 C153.1 C154.1 C155.2 C156.2 C157.2 C162.2 C163.2 C164.2 C165.2 C166.2 C167.2 C168.2 C169.1 C170.2 C175.2 C176.2 C177.1 C179.2 C180.1 C181.2 C182.2 C184.2 C185.1 C186.2 C189.1 C191.1 C192.2 C194.1 C195.2 C196.2 C197.1 C199.2 C200.2 C201.2 C202.2 C203.2 C205.1 C206.2 C207.2 C208.1 C209.2 C214.2 C215.2 C216.2 C218.2 C219.2 C220.1 C221.2 C222.2 C224.2 C228.2 C230.2 C233.1 C235.1 C236.2 C237.1 C239.1 C241.1 C242.2 C243.2 C244.1 C245.1 C247.1 C249.1 C250.2 C251.1 C252.2 C253.2 C255.1 C258.2 C259.2 C260.1 C262.1 C273.2 C274.1 C275.2 C276.2 C277.1 C278.2 C280.2 C281.2 C282.2 C283.2 C284.2 C285.2 C286.1 C287.2 C288.1 C289.2 C290.2 C291.1 C292.2 C293.2 C294.2 C295.1 C296.1 C297.2 C299.2 C300.2 C301.2 C302.2 C303.2 C304.2 C305.2 C306.2 C307.2 C308.2 C309.1 C310.2 C311.2 C312.2 C313.2 C314.2 C315.2 C316.2 C317.2 C318.2 C319.2 C320.2 C321.2 C322.2 C323.1 C324.2 C325.2 C326.2 C327.2 C328.2 C329.2 C330.2 C331.2 C332.2 C333.2 C334.2 C335.2 C336.2 C337.2 C338.2 C339.2 C340.2 C341.2 C343.1 C344.2 C345.1 C346.2 C347.2 C352.2 C355.2 C356.2 C357.2 C358.2 C359.2 C360.2 C362.1 C363.2 C364.1 C365.1 C366.2 CN1.6 CN1.12 CN1.15 CN1.18 CN1.21 CN1.24 CN1.27 CN1.30 CN1.31 CN1.34 CN1.37 CN1.40 CN1.43 CN1.46 CN1.49 CN1.55 CN1.60 CN2.8 CN2.10 CN2.12 CN2.14 CN3.3 CN3.6 CN4.2 CN5.4 CN5.9 CN5.15 CN5.18 CN5.21 CN5.26 CN5.27 CN5.29 CN5.34 CN5.35 CN5.37 CN5.40 CN5.43 CN5.50 CN6.13 CN6.18 CN6.21 CN6.24 CN6.27 CN6.30 CN6.35 CN6.41 CN6.42 CN6.43 CN6.44 CN6.45 CN7.1 CN7.4 CN7.7 CN7.10 CN7.13 CN7.15 CN7.21 CN7.22 CN7.23 CN7.24 CN8.7 CN8.10 CN8.13 CN8.21 CN8.24 CN9.1 CN9.2 CN9.3 CN9.10 CN9.11 CN10.1 CN10.2 CN10.3 CN11.8 CN12.4 CN13.3 CN13.6 CN13.9 CN14.4 CN14.9 CN14.15 CN14.18 CN14.21 CN14.26 CN14.27 CN14.29 CN14.34 CN14.35 CN14.37 CN14.40 CN14.43 CN14.50 EC1.2 EC2.2 EC3.2 EC4.2 EC5.2 EC6.2 EC7.2 EC8.2 EC9.2 EC10.1 EC11.2 EC12.2 EC13.1 EC14.1 EC15.2 FAN1.3 H1.1 H2.1(PIN1) H3.1(PIN1) H4.1(PIN1) H5.1 H6.1 H7.1 H8.1(PIN1) H9.1 H10.1 H11.1(PIN1) JDIM1.2 JDIM1.3 JDIM1.8 JDIM1.9 JDIM1.11 JDIM1.13 JDIM1.14 JDIM1.19 JDIM1.20 JDIM1.25 JDIM1.26 JDIM1.28 JDIM1.31 JDIM1.32 JDIM1.37 JDIM1.38 JDIM1.43 JDIM1.44 JDIM1.46 JDIM1.48 JDIM1.49 JDIM1.54 JDIM1.55 JDIM1.60 JDIM1.61 JDIM1.63 JDIM1.65 JDIM1.66 JDIM1.71 JDIM1.72 JDIM1.127 JDIM1.128 JDIM1.133 JDIM1.134 JDIM1.136 JDIM1.138 JDIM1.139 JDIM1.144 JDIM1.145 JDIM1.150 JDIM1.151 JDIM1.153 JDIM1.155 JDIM1.156 JDIM1.161 JDIM1.162 JDIM1.167 JDIM1.168 JDIM1.170 JDIM1.172 JDIM1.173 JDIM1.178 JDIM1.179 JDIM1.184 JDIM1.185 JDIM1.187 JDIM1.189 JDIM1.190 JDIM1.195 JDIM1.196 PC1.2 PC2.2 PC3.2 PC4.2 PC5.1 PC6.2 PC7.2 PC8.2 PC9.2 PC10.2 PC15.2 PC16.2 PC17.1 PC18.1 PC19.1 PC20.1 PC23.1 PC24.1 PC26.1 PC28.1 PC29.1 PC32.2 PC33.2 PC34.2 PC35.2 PC36.2 PC37.2 PC38.1 PC39.2 PC40.1 PC41.2 PC42.1 PC43.1 PC44.2 PC45.2 PC46.2 PC48.2 PC49.2 PC51.1 PC52.1 PC54.1 PC55.1 PC56.2 PC57.2 PC58.2 PC59.1 PC62.2 PC63.2 PC65.2 PC66.2 PC67.2 PC68.2 PC69.2 PC70.2 PC71.2 PC72.2 PC73.1 PC74.2 PC75.1 PC76.2 PC77.1 PC78.2 PC79.1 PC80.2 PC81.2 PC82.2 PC84.1 PC86.1 PC87.1 PC88.2 PC89.2 PC90.2 PC91.2 PC92.2 PC93.2 PC94.2 PC95.2 PC96.1 PC97.2 PC98.2 PC99.2 PC100.1 PC101.2 PC102.2 PC104.2 PC105.2 PC106.2 PC107.2 PC108.2 PC109.2 PC110.2 PC111.2 PC112.1 PC113.2 PC114.2 PC115.2 PC116.2 PC118.2 PC120.2 PC121.2 PC122.1 PC123.1 PC125.2 PC126.2 PC127.2 PC128.2 PC129.2 PC130.2 PC131.1 PC133.2 PC134.2 PC135.2 PC136.2 PC137.2 PC138.2 PC139.2 PC140.1 PC141.2 PC142.2 PC144.2 PC145.2 PC146.2 PC147.2 PC148.2 PC149.1 PC150.1 PC151.2 PC152.1 PD1.2 PD3.2 PD6.2 PD7.2 PD8.2 PQ1.1 PQ1.2 PQ1.3 PQ3.5 PQ3.6 PQ3.7 PQ4.1 PQ8.1 PQ9.1 PQ14.1 PQ14.2 PQ14.3 PR7.2 PR9.2 PR11.1 PR23.2 PR27.2 PR28.2 PR33.2 PR44.2 PR47.1 PR62.2 PR67.2 PR74.1 PR81.2 PR87.2 PR91.1 PR94.1 PR108.2 PR111.1 PR112.1 PR123.2 PR127.1 PR128.1 PU1.4 PU1.12 PU1.13 PU1.14 PU1.15 PU1.19 PU2.2 PU3.11 PU4.2 PU4.14 PU5.2 PU5.14 PU6.21 PU7.14 PU7.21 PU7.22 PU7.23 PU7.24 PU7.25 PU8.4 PU8.7 PU8.10 PU8.21 Q2.1 Q3.1 Q6.1 Q9.1 Q11.1 Q16.1 Q16.4 Q19.1 Q19.4 Q25.1 Q26.1 Q30.1 Q30.4 R10.2 R11.2 R12.2 R17.2 R20.1 R26.2 R29.2 R30.2 R45.1 R60.1 R66.1 R71.1 R72.1 R73.1 R76.1 R78.1 R80.1 R81.2 R85.2 R88.1 R90.2 R91.1 R92.1 R95.2 R97.1 R101.2 R109.2 R111.2 R115.2 R123.1 R126.2 R127.2 R134.2 R138.1 R146.1 R148.1 R150.2 R166.2 R167.2 R170.2 R171.2 R172.2 R176.2 R182.2 R183.2 R195.2 R200.1 R227.1 R231.2 R232.2 R233.2 R234.2 R242.1 R245.1 R250.2 R251.2 R255.2 R262.2 R270.1 R303.2 R306.2 R321.2 R323.2 R336.1 R353.1 R354.2 R357.2 R359.1 R361.1 R362.1 R367.2 R380.2 R383.1 R392.2 R393.2 R394.2 R395.2 R399.1 R409.2 R414.1 R417.2 R432.2 R434.2 R435.1 R439.1 R440.1 R458.2 R461.2 R465.2 R470.1 U1.7 U1.10 U1.11 U3.7 U3.15 U4.2 U5.12 U5.18 U5.31 U5.47 U5.63 U6.2 U7.11 U7.24 U7.35 U7.94 U7.113 U8.2 U9.4 U10.3 U10.13 U10.21 U11.3 U12.6 U12.10 U12.18 U12.21 U12.25 U12.26 U12.27 U12.28 U12.29 U12.30 U12.31 U12.32 U12.33 U12.34 U13.5 U14.2 U15.4 U15.8 U15.11 U15.18 U15.25 U16.3 U17.2 U18.34 U18.35 U18.41 U20.A11 U20.A14 U20.A18 U20.A24 U20.A28 U20.A32 U20.A36 U20.A40 U20.A44 U20.A48 U20.A52 U20.A56 U20.AA1 U20.AA58 U20.AB7 U20.AB10 U20.AB20 U20.AB22 U20.AC61 U20.AD3 U20.AD21 U20.AD63 U20.AE5 U20.AE10 U20.AE58 U20.AF11 U20.AF12 U20.AF14 U20.AF15 U20.AF17 U20.AF18 U20.AG1 U20.AG11 U20.AG21 U20.AG23 U20.AG60 U20.AG61 U20.AG62 U20.AG63 U20.AH16 U20.AH17 U20.AH19 U20.AH20 U20.AH22 U20.AH24 U20.AH28 U20.AH30 U20.AH32 U20.AH34 U20.AH36 U20.AH38 U20.AH40 U20.AH42 U20.AH44 U20.AH46 U20.AH49 U20.AH51 U20.AH53 U20.AH55 U20.AH57 U20.AJ13 U20.AJ14 U20.AJ23 U20.AJ25 U20.AJ27 U20.AJ29 U20.AJ35 U20.AJ39 U20.AJ41 U20.AJ43 U20.AJ45 U20.AJ47 U20.AJ50 U20.AJ52 U20.AJ54 U20.AJ56 U20.AJ58 U20.AJ60 U20.AJ63 U20.AK3 U20.AK23 U20.AK52 U20.AL10 U20.AL13 U20.AL17 U20.AL20 U20.AL22 U20.AL23 U20.AL26 U20.AL29 U20.AL31 U20.AL33 U20.AL36 U20.AL39 U20.AL40 U20.AL45 U20.AL46 U20.AL51 U20.AL52 U20.AL54 U20.AL57 U20.AL60 U20.AL61 U20.AM1 U20.AM17 U20.AM23 U20.AM31 U20.AM52 U20.AN7 U20.AN17 U20.AN23 U20.AN31 U20.AN32 U20.AN35 U20.AN36 U20.AN39 U20.AN40 U20.AN42 U20.AN43 U20.AN45 U20.AN46 U20.AN48 U20.AN49 U20.AN51 U20.AN52 U20.AN60 U20.AN63 U20.AP3 U20.AP10 U20.AP17 U20.AP20 U20.AP22 U20.AP23 U20.AP26 U20.AP29 U20.AP31 U20.AP38 U20.AP39 U20.AP48 U20.AP52 U20.AP54 U20.AP57 U20.AR5 U20.AR11 U20.AR15 U20.AR17 U20.AR23 U20.AR31 U20.AR33 U20.AR39 U20.AR43 U20.AR49 U20.AR52 U20.AT13 U20.AT35 U20.AT37 U20.AT40 U20.AT42 U20.AT43 U20.AT46 U20.AT49 U20.AT61 U20.AT62 U20.AT63 U20.AU1 U20.AU16 U20.AU18 U20.AU20 U20.AU22 U20.AU24 U20.AU26 U20.AU28 U20.AU30 U20.AU33 U20.AU51 U20.AU53 U20.AU55 U20.AU57 U20.AU59 U20.AV8 U20.AV14 U20.AV16 U20.AV20 U20.AV24 U20.AV28 U20.AV33 U20.AV34 U20.AV36 U20.AV39 U20.AV41 U20.AV43 U20.AV46 U20.AV49 U20.AV51 U20.AV55 U20.AV59 U20.AW4 U20.AW16 U20.AW24 U20.AW33 U20.AW35 U20.AW37 U20.AW40 U20.AW42 U20.AW44 U20.AW47 U20.AW50 U20.AW51 U20.AW59 U20.AW60 U20.AY4 U20.AY6 U20.AY11 U20.AY16 U20.AY18 U20.AY22 U20.AY24 U20.AY26 U20.AY30 U20.AY33 U20.AY51 U20.AY53 U20.AY57 U20.AY59 U20.B4 U20.B20 U20.B24 U20.B26 U20.B28 U20.B32 U20.B36 U20.B40 U20.B44 U20.B48 U20.B52 U20.B56 U20.B60 U20.C11 U20.C14 U20.C18 U20.C20 U20.C25 U20.C27 U20.C38 U20.C39 U20.C57 U20.D2 U20.D5 U20.D8 U20.D12 U20.D14 U20.D18 U20.D21 U20.D23 U20.D25 U20.D26 U20.D27 U20.D29 U20.D30 U20.D31 U20.D33 U20.D34 U20.D35 U20.D37 U20.D38 U20.D39 U20.D41 U20.D42 U20.D43 U20.D45 U20.D46 U20.D47 U20.D49 U20.D50 U20.D51 U20.D53 U20.D54 U20.D55 U20.D57 U20.D59 U20.D62 U20.D63 U20.E11 U20.E17 U20.F20 U20.F26 U20.F30 U20.F34 U20.F38 U20.F42 U20.F46 U20.F50 U20.F54 U20.F58 U20.F61 U20.G3 U20.G5 U20.G6 U20.G8 U20.G18 U20.G22 U20.H13 U20.H17 U20.H57 U20.J10 U20.J22 U20.J59 U20.J63 U20.K1 U20.K12 U20.L7 U20.L13 U20.L15 U20.L17 U20.L18 U20.L20 U20.L58 U20.L61 U20.M22 U20.N3 U20.N10 U20.N21 U20.P22 U20.P59 U20.P62 U20.P63 U20.R8 U20.R10 U20.R22 U20.T1 U20.T58 U20.U9 U20.U20 U20.U22 U20.U61 U20.V3 U20.V7 U20.V10 U20.V23 U20.V58 U20.W20 U20.W22 U20.Y10 U20.Y59 U20.Y63 U21.5 U22.3 U23.8 U23.9 U23.10 U23.11 U23.12 U23.13 Y2.2 Y2.4
VCC_SENSE: PR45.2 R243.1 U20.E63
VCCRTC_1: Q1.3 R19.1
VCCRTC_3: Q1.2 R21.2 R30.1
VCCST_PWRGD_XDP: CN1.50 R240.2
VSS_SENSE: PR41.2 R251.1 U20.E62
1237BSTPCH: PR16.2 PU1.20
1237ENPCH: PC5.2 PR4.1 PU1.2
1237FBPCH: PR8.1 PR9.1 PU1.5
1237FBPCH_S: PR8.2 PR85.1
1237LX: PC21.2 PL9.1 PR36.2 PU1.10 PU1.11 PU1.16 PU1.17 PU1.18
1237PFMPCH: PR7.1 PU1.3
1237PGPCH: PR5.1 PU1.1
1237SSPCH: PC6.1 PU1.23
3920_RST#: C29.1 Q4.3 Q8.3 Q19.2 R26.1 R33.2 U4.5 U7.37
8008LX1.5V: PL2.1 PU2.3
51216DRVH: PQ15.4 PU8.14
51216DRVL: PQ14.4 PU8.11
51216MODE: PR128.2 PU8.19
51216PG: PR130.1 PU8.20
51216REFIN: PC138.1 PR123.1 PR124.2 PU8.8
51216S3: PR129.1 PU8.17 R463.2
51216S5: PR131.1 PU8.16
51216SW: PC143.2 PL14.1 PQ14.5 PQ14.6 PQ14.7 PQ14.8 PQ15.1 PQ15.2 PQ15.3 PR132.2 PU8.13
51216TRIP: PR127.2 PU8.18
81101_BST: PC53.1 PU3.8
81101_HG: PR69.1 PU3.9
81101_HG_G: PQ3.1 PR69.2
81101_LG: PQ3.8 PU3.12
81101_PH: PC53.2 PL7.1 PQ3.9 PR38.2 PR39.2 PU3.10
81101COM: PC30.2 PR19.2 PU3.23
81101DIFFOUT: PR31.1 PR32.1 PU3.25
81101FB: PC22.1 PC30.1 PC31.2 PR18.1 PR31.2 PU3.24
81101ILIM: PR12.2 PU3.21
81101IOUT: PC13.1 PR13.2 PU3.20
81101ROSC: PR20.2 PU3.22
81181_AGND: PC12.1 PC13.2 PC27.2 PC61.1 PC64.2 PR13.1 PR14.1 PR15.2 PR20.1 PR74.2 PU3.29
+BATCHG: PC119.2 PC127.1 PC128.1 PC129.1 PC130.1 PC134.1 PD6.1 PL12.1 PL13.1 PQ6.1 PQ6.2 PQ6.3 PR102.1 PR103.2 PR105.2
+LCDVCC: L8.2 U8.1
+PCH_VCCDSW: C5.1 C288.2 TP43.1 U20.AG19 U20.AG20
+PRWSRC: PC132.1 PQ6.5 PQ7.3 PQ13.5 PQ13.6 PQ13.7 PQ13.8 PR98.1 PR106.2 PR113.2 PR115.2 PR117.1
+SMDDR_VREF_DIMM: C312.1 C337.1 JDIM1.126 R461.1 R466.2 R467.2 R468.1
+SMDDR_VREF_DQ1: C280.1 C282.1 JDIM1.1 R387.2
+VA: CN6.7 PD5.2
+VA_AIR: PD5.1 PR34.1 PR58.1
+VAD: C146.1 C147.2 C148.1 CN6.1 CN6.2 CN6.3 CN6.4 CN6.5 CN6.6 PC97.1 PC124.1 PD3.1 PQ7.4 PQ12.4 PQ13.1 PQ13.2 PQ13.3 PR50.2 PR83.1 PR92.2 PR100.1
AC_LED_ON#: CN6.11 R223.2 U7.92
AC_PRESENT_EC: R236.2 R388.1
AC_PRESENT_R: R385.1 R388.2 U20.AJ8
ACC_INT1: U1.5 U5.26
ACC_INT2: U1.4 U5.27
ACCEL_INTA#: R381.1 U20.AG3
ACIN: PR93.1 PR108.1 PR109.1 PU7.5 U7.76
ACZ_BCLK: R419.2 U20.AW8
ACZ_RST#: R418.2 U20.AU8
ACZ_RST#_AUDIO: Q18.1 R418.1 U18.11
ACZ_SDIN0: C247.2 R289.1 U20.AY10
ACZ_SDOUT: R411.2 R420.2 U20.AU11
ACZ_SDOUT_AUDIO: C237.2 R411.1 U18.5
ACZ_SPKR: Q23.2 R309.1
ACZ_SYNC: R412.2 R421.2 U20.AV11
ACZ_SYNC_AUDIO: C255.2 R421.1 U18.10
AD_AIR: PC44.1 PR44.1 PR58.2 U7.65
AD_ID: C24.1 CN6.10 R36.2
AD_TYPE: R35.1 U7.64
ALERT#: PR56.1 PR90.2 PU3.4
ALS_INT: CN3.2 R47.1 U5.36
AMP_BEEP: C263.2 U18.12
AMP_BEEP_L: C263.1 C271.1 R339.2 R340.1
AMP_BEEP_R2: C270.2 R339.1
AMP_CLK: R319.1 R332.1 U19.8
AMP_DAT: R318.1 R331.1 U19.7
B_TEMP_MBAT: CN9.4 PC131.2 PR118.1 PR119.2
BASE_EC_KEY_R: Q15.2 R102.2
BASE_EC_RESET#: CN8.15 Q14.3 R483.1
BASE_EC_RESET_R: Q14.2 R103.2
BATDIS_G: PC124.2 PC132.2 PQ7.1 PR107.2
BATDIS_ID_DOD: PC119.1 PQ6.4 PR104.1
BATSHIP: PQ9.2 U7.71
BATT+: CN9.7 CN9.8 CN9.9 PC133.1 PL12.2 PL13.2
BIOS_CS#: R145.2 U7.128
BIOS_RD#: R229.2 U7.119
BIOS_SPI_CLK: R144.2 U7.126
BIOS_WP#: R112.1 R131.1 TP68.1 U9.3
BIOS_WR#: R210.2 U7.120
BIT_CLK_AUDIO: C239.2 C296.2 R275.2 R419.1
BLON_CON: C205.2 CN7.16 D9.1 R250.1
BOARD_ID0: R352.1 R353.2 U20.AG6
BOARD_ID1: R413.1 R414.2 U20.AP1
BOARD_ID2: R399.2 R400.1 U20.AL4
BOARD_ID3: R435.2 R438.1 TP59.1 U20.AT5
BOARD_ID4: R358.1 R359.2 U20.AG5
BOARD_ID5: R325.1 R336.2 U20.AB6
BPM#2: TP14.1 U20.H61
BPM#3: TP15.1 U20.H62
BPM#4: TP17.1 U20.K59
BPM#5: TP84.1 U20.H63
BPM#6: TP16.1 U20.K60
BPM#7: TP24.1 U20.J61
BQACDRV: PR107.1 PU7.4
BQB_1: PC103.1 PD4.1 PR86.1
BQB_2: PR86.2 PU7.17
BQBATDRV: PR104.2 PU7.11
BQCLK: PR95.1 PU7.9
BQCMSRC: PR106.1 PU7.3
BQDATA: PR96.1 PU7.8
BQHIDRV: PQ2.4 PU7.18
BQIOUT: PC113.1 PR99.2 PU7.7
BQLODRV: PQ1.4 PU7.15
BQLR: PL11.2 PR101.2 PR103.1
BQPHASE: PC103.2 PL11.1 PQ1.5 PQ1.6 PQ1.7 PQ1.8 PQ2.1 PQ2.2 PQ2.3 PR42.2 PU7.19
BQSRN: PR80.2 PU7.12
BQSRP: PR79.2 PU7.13
BQVCC: PC115.1 PR100.2 PU7.20
BT_COMBO_EN#: R124.2 R188.1 TP30.1 U20.U4
BT_OFF: Q2.2 R374.1 TP93.1 U20.AM3
BUTTON_ONKEY_R: R27.2 R28.1 U4.4
C_TX0_HDMI+: C102.2 CN6.22 R117.1
C_TX0_HDMI-: C101.2 CN6.23 R117.2
C_TX1_HDMI+: C143.2 CN6.25 R157.1
C_TX1_HDMI-: C142.2 CN6.26 R157.2
C_TX2_HDMI+: C141.2 CN6.28 R156.1
C_TX2_HDMI-: C140.2 CN6.29 R156.2
C_TXC_HDMI+: C145.2 CN6.19 R158.1
C_TXC_HDMI-: C144.2 CN6.20 R158.2
CAP+: C248.2 U18.28
CAP-: C248.1 U18.27
CATERR#: TP21.1 U20.K61
CFG0: R366.1 TP91.1 U20.AC60
CFG1: CN1.36 TP60.1 U20.AC62
CFG2: CN1.38 TP37.1 U20.AC63
CFG3: CN1.39 R323.1 R344.2 TP89.1 U20.AA63
CFG4: CN1.44 R354.1 TP46.1 U20.AA60
CFG5: CN1.45 TP33.1 U20.Y62
CFG6: CN1.47 TP42.1 U20.Y61
CFG7: CN1.48 TP36.1 U20.Y60
CFG8: CN1.26 TP31.1 U20.V62
CFG9: CN1.25 TP54.1 U20.V61
CFG10: CN1.23 TP53.1 U20.V60
CFG11: CN1.22 TP32.1 U20.U60
CFG12: CN1.17 TP50.1 U20.T63
CFG13: CN1.16 TP19.1 U20.T62
CFG14: CN1.14 TP47.1 U20.T61
CFG15: CN1.13 TP41.1 U20.T60
CFG16: CN1.28 TP56.1 U20.AA62
CFG17: CN1.29 TP58.1 U20.AA61
CFG18: CN1.19 TP27.1 U20.U63
CFG19: CN1.20 TP28.1 U20.U62
CFG_RCOMP: R306.1 U20.V63
CHIP_DOCK_DET#: Q16.3 R365.1
CK_XDP_N: CN1.10 RP4.1
CK_XDP_N_R: RP4.2 U20.B35
CK_XDP_P: CN1.11 RP4.3
CK_XDP_P_R: RP4.4 U20.A35
CLK_24M_DEBUG: CN5.19 EC13.2 R110.2 R453.2
CLK_24M_KBC: EC14.2 R108.1 R454.2 U7.12
CLK_24M_TPM: EC10.2 R297.2 R298.2 U15.21
CLK_PCI_EC_R: R454.1 U20.AN15
CLK_PCI_LPC_R: R298.1 R453.1 U20.AP15
CLK_PCIE_CRN: CN13.8 U20.B41
CLK_PCIE_CRP: CN13.7 U20.A41
CLK_PCIE_WLANN: CN5.11 U20.C41
CLK_PCIE_WLANP: CN5.13 U20.B42
CLKRUN#: R290.2 U7.38 U15.15 U20.V5
CPUOVERT: D2.2 Q8.1 R113.1 U13.4
CPVSS: C227.2 C232.2 C238.1 C256.1 C261.1 R10.1
CRY1: R236.1 U7.122
CRY2: C197.2 R227.2 R228.1 U7.123
CSCOMP: PC11.1 PC14.1 PR2.1 PR12.1 PR29.1 PU3.19
CSIN: PC117.2 PC121.1 PR116.1 PU7.1
CSIP: PC117.1 PC122.2 PR115.1 PU7.2
CSON: PC83.2 PC89.1 PR80.1 PR105.1
CSOP: PC83.1 PC88.1 PR79.1 PR101.1
CSREF: PC12.2 PR10.1 PU3.17
CSSUM: PC11.2 PC14.2 PR1.1 PR3.1 PU3.18
DC_TEST_A3_B3: U20.A3 U20.B3
DC_TEST_A61_B61: U20.A61 U20.B61
DC_TEST_AY2_AW2: U20.AW2 U20.AY2
DC_TEST_AY3_AW3: U20.AW3 U20.AY3
DC_TEST_AY61_AW61: U20.AW61 U20.AY61
DC_TEST_AY62_AW62: U20.AW62 U20.AY62
DC_TEST_B62_B63: U20.B62 U20.B63
DC_TEST_C1_C2: U20.C1 U20.C2
DCAP: PC96.2 PU6.16
DDR3_DRAMRST#: C309.2 JDIM1.30 R455.1 R456.2
DDR_PG_CNTL: Q25.2 U20.AV61 U22.2
DDR_THERMDA: C298.1 Q24.2 Q24.3 U21.2
DDR_THERMDC: C298.2 Q24.1 U21.3
DDR_VTT_PG_CTRL: Q26.3 Q27.2 R463.1 R464.2 R465.1 U22.4
DDR_VTTREF: PC137.1 PR122.1 R355.1 R468.2
DE1_1: R163.2 R183.1 U12.3
DE2_1: R149.2 R150.1 U12.16
DEVSLP0: R198.1 U20.P2
DEVSLP1: R202.1 R472.1 U20.L2
DEVSLP2: R208.1 U20.N5
DGPU_PWROK: R191.1 U20.T3
DIGITAL_CLK: C56.1 C224.1 L4.1 R263.1
DIGITAL_CLK_R: C40.2 CN3.7 L4.2
DIGITAL_D1: C51.1 C228.1 L3.1 R267.2
DIGITAL_D1_R: C39.2 CN3.8 L3.2
DIMM1_SA0: JDIM1.197 R458.1
DIMM1_SA1: JDIM1.201 R457.1
DMIC0: R267.1 U18.3
DMIC_CLK_R: R263.2 U18.2
DNBSWON#: CN1.51 R375.1 R441.2 U7.90
DNBSWON#_R: R375.2 R389.1 U20.AL7
DOCK_DET_R: D6.1 Q16.5 Q16.6 R100.2 U7.36
DOCK_ECBASE_INT#: CN8.17 Q15.1
DOCK_IN_DET: CN8.5 Q16.2 R220.2
DPWROK: R398.1 R401.1 U20.AV5
DPWROK_EC: R392.1 R398.2 U7.117
DSWVRMEN: R415.1 U20.AW7
EC_AOCS#: Q3.2 U7.18
EC_BASE_EN: D6.2 R102.1 R103.1 R257.1 R480.2 U7.50
EC_DEBUG: R1.2 R54.2
EC_HW_STRAP: R37.2 U7.42
EC_PCIE_WAKE#: Q13.3 R16.2 U7.73
EC_PECI: R83.1 U20.N62
EC_PECI_R: R83.2 U7.118
EC_PWROK: D4.1 R230.2 R242.2 U7.93 U16.1 U20.AB5 U20.AY7
EC_RCIN#: R189.1 U7.2 U20.V4
ECBASE_CLK: Q20.1 R178.2 U7.83
ECBASE_CLK_R: CN8.18 Q20.6
ECBASE_DATA: Q20.4 R186.2 R484.1 U7.84
ECBASE_DATA_R: CN8.14 Q20.3
ECBASE_INT#: Q15.3 R104.2 U7.31
EDP_AUXN_R: C204.1 CN7.9
EDP_AUXP_R: C198.1 CN7.8
EDP_DISP_UTIL: R168.1 U20.A43
EDP_HPD_L: Q11.2 R90.1 R94.2 R256.2
EDP_HPD_R: CN7.14 R256.1
EDP_RCOMP: R181.2 U20.D20
EDP_TXN0_R: C188.1 CN7.5
EDP_TXN1_R: C178.1 CN7.2
EDP_TXP0_R: C190.1 CN7.6
EDP_TXP1_R: C183.1 CN7.3
EMU_LID: R143.1 U7.25
EQ1_1: R182.1 R192.2 U12.2
EQ2_1: R165.2 R166.1 U12.17
EXT_MIC_L: CN8.2 R341.1
EXT_MIC_L1: C272.1 U18.17
EXT_MIC_R1: C272.2 R322.2 R341.2 U18.18
FAN1_PWM: C341.1 FAN1.2 U7.26
FAN1SIG: C340.1 FAN1.4 R469.1 U7.28
G5934CN: PC85.2 PU6.19
G5934CP: PC85.1 PU6.18
G5934DISC1: PR65.2 PU6.5
G5934DISC2: PR73.2 PU6.6
G5934DISC4: PR77.1 PU6.8
G5934PG: PR93.2 PU6.15
G5934VIN: PC75.2 PR50.1 PU6.20
G5934VOUT: PC91.1 PU6.17
G5934VSENSE: PR91.2 PR92.1 PU6.14
GPIO13_ULT: R406.1 R425.2 U20.AT3
GPIO14_ULT: R363.1 TP48.1 U20.AH4
GPIO15_ULT: R349.2 U20.AD6
GPIO16_ULT: R320.1 TP90.1 U20.Y1
GPIO24_ULT: R333.1 U20.AD5
GPIO25_ULT: R365.2 R368.1 U20.AM4
GPIO26_ULT: R408.1 U20.AN3
GPIO27_EC: R391.1 U7.23
GPIO27_ULT: R391.2 R402.1 U20.AN5
GPIO28_ULT: R348.1 U20.AD7
GPIO33_EC: D8.1 R201.2 R420.1
GPIO42_EC: R12.1 R13.2 U7.75
GPIO44_ULT: R364.1 U20.AK4
GPIO50_ULT: R274.2 R288.1 U20.P3
GPIO52_ULT: R218.1 R239.2 U20.L1
GPIO66_ULT: R148.2 R160.2 U20.D3
GPIO70_ULT: R177.1 U20.C4
GPIO76_ULT: R287.1 TP86.1 U20.P1
GPIO77_ULT: R217.1 U20.U6
GPIO86_ULT: TP25.1 U20.L8
GSPI0_CLK: RP2.4 U20.L6
GSPI0_CS: RP1.3 U20.R6
GSPI0_MISO: RP2.6 U20.N6
GSPI1_CLK: RP3.1 U20.L5
GSPI1_CS: RP1.2 U20.R7
GSPI1_MISO: RP1.4 U20.N7
GSPI1_MOSI: RP1.1 U20.K2
GYRO_INT1: U5.28 U23.7
GYRO_INT2: U5.55 U23.6
H_CPU_SVIDALRT#: R276.1 U20.L62
H_CPU_SVIDDAT: R265.1 U20.L63
H_PROCHOT#: C66.2 PR54.2 PR75.2 Q9.3 R261.1 R266.1
H_PROCHOT#_EC: Q9.2 R92.2 U7.15
H_SYS_PWROK_XDP: C274.2 CN1.54 R326.1 R342.2
H_VCCST_PWRGD: C154.2 D5.2 R114.1 R121.2 R240.1 U11.4
H_VCCST_PWRGD_R: R121.1 U20.B59
H_VR_ENABLE_MCP: PR53.1 R175.2 U20.F60
HD_BCLK: R275.1 U18.6
HD_SDIN0: R289.2 U18.8
HDMI_HPD_CON: CN8.19 R197.1 U20.C8
HOLD#: R141.2 R153.2 TP69.1 U9.7
HOME_BUTTON_EC: Q30.5 R477.2 U7.97
HOME_BUTTON_INT#: CN11.3 R116.2 R479.2 U7.27
HOME_BUTTON_LED: CN11.5 Q30.2 R209.2
HOME_BUTTON_LED#: CN8.16 Q30.3 Q30.6
HOME_BUTTON_SLEEP: TP7.1 U7.70
HOME_BUTTONE POWER: C220.2 CN11.4 R259.1 R478.1
HPOUT_L: C223.1 R292.2 U18.23
HPOUT_L_1: C223.2 U19.1
HPOUT_R: C264.1 R296.2 U18.24
HPOUT_R_1: C264.2 U19.5
HWPG: C89.2 D5.1 PR5.2 PR26.2 PR46.2 PR68.2 PR84.2 PR130.2 U3.1 U3.4 U3.10 U3.13 U7.14 U11.2
I2C0_SCL: RP3.8 U20.F3
I2C0_SDA: RP2.8 U20.F2
I2C1_SCL: CN3.4 R18.1 U1.2 U5.58 U23.2
I2C1_SCL_PCH: RP3.9 U20.F1
I2C1_SDA: CN3.5 R14.1 U1.3 U5.59 U23.3
I2C1_SDA_PCH: RP3.3 U20.G4
IDEA_G: PQ12.3 PQ13.4 PR112.2
IMVP_PWRGD: D7.1 PR60.2 PR61.1 R196.2 U16.2
IMVP_PWRGD_R: D7.2 R40.2 R175.1 R196.1 U20.C59
IN_CLK: C145.1 U20.B57
IN_CLK#: C144.1 U20.A57
IN_D0: C102.1 U20.A55
IN_D0#: C101.1 U20.B55
IN_D1: C143.1 U20.C58
IN_D1#: C142.1 U20.B58
IN_D2: C141.1 U20.C55
IN_D2#: C140.1 U20.C54
INT_BT_OFF#: CN5.51 Q2.3 R41.2 R42.1
INT_EDP_AUXN: C204.2 U20.A45
INT_EDP_AUXP: C198.2 U20.B45
INT_EDP_HPD: Q10.3 Q11.3 R81.1 R82.1 R93.2 R94.1
INT_EDP_HPD_Q: Q10.1 R85.1 R93.1 U20.D6
INT_EDP_TXN0: C188.2 U20.C45
INT_EDP_TXN1: C178.2 U20.A47
INT_EDP_TXP0: C190.2 U20.B46
INT_EDP_TXP1: C183.2 U20.B47
INT_RF_OFF#: CN5.20 Q6.3 R57.1
IO_THERMDA_IO: C114.1 Q17.2 Q17.3 U13.2
IO_THERMDC_IO: C114.2 Q17.1 U13.3
JTAG_TCK_PCH: R295.1 R301.1 R362.2 U20.AE62
JTAG_TDI_PCH: R343.2 R424.1 U20.AD61
JTAG_TDO_PCH: R347.2 R429.2 R433.1 U20.AE61
JTAG_TMS_PCH: R329.2 R416.1 U20.AD62
JTAGX_PCH: R278.1 R351.2 R436.1 U20.AE63
L_SPK+: C213.1 CN6.36 U18.32
L_SPK-: C212.1 CN6.37 U18.33
LAD0: CN5.16 R284.2 U7.10 U20.AU14
LAD0_T: R284.1 U15.26
LAD1: CN5.14 R283.2 U7.8 U20.AW12
LAD1_T: R283.1 U15.23
LAD2: CN5.12 R281.2 U7.7 U20.AY12
LAD2_T: R281.1 U15.20
LAD3: CN5.10 R280.2 U7.5 U20.AW11
LAD3_T: R280.1 U15.17
LAN_DISABLE#: R405.1 U20.AM7
LFRAME#: CN5.8 R282.2 U7.4 U20.AV12
LFRAME#_T: R282.1 U15.22
LID_EC#: C311.1 CN13.14 R226.2 U7.127
LINEOUT_L: R279.2 U19.14
LINEOUT_L_C: C246.2 CN8.3 R279.1 R292.1
LINEOUT_R: R316.2 U19.11
LINEOUT_R_C: C257.2 CN8.4 R296.1 R316.1
LPCPD#_TPM: R286.2 U15.28
M_B_A0: JDIM1.98 U20.AP40
M_B_A1: JDIM1.97 U20.AR40
M_B_A2: JDIM1.96 U20.AP42
M_B_A3: JDIM1.95 U20.AR42
M_B_A4: JDIM1.92 U20.AR45
M_B_A5: JDIM1.91 U20.AP45
M_B_A6: JDIM1.90 U20.AW46
M_B_A7: JDIM1.86 U20.AY46
M_B_A8: JDIM1.89 U20.AY47
M_B_A9: JDIM1.85 U20.AU46
M_B_A10: JDIM1.107 U20.AK36
M_B_A11: JDIM1.84 U20.AV47
M_B_A12: JDIM1.83 U20.AU47
M_B_A13: JDIM1.119 U20.AK33
M_B_A14: JDIM1.80 U20.AR46
M_B_A15: JDIM1.78 U20.AP46
M_B_BS#0: JDIM1.109 U20.AL35
M_B_BS#1: JDIM1.108 U20.AM36
M_B_BS#2: JDIM1.79 U20.AU49
M_B_CAS#: JDIM1.115 U20.AM33
M_B_CKE0: JDIM1.73 U20.AY49
M_B_CKE1: JDIM1.74 U20.AU50
M_B_CLKN0: JDIM1.103 U20.AM38
M_B_CLKN1: JDIM1.104 U20.AK38
M_B_CLKP0: JDIM1.101 U20.AN38
M_B_CLKP1: JDIM1.102 U20.AL38
M_B_CS#0: JDIM1.114 U20.AM32
M_B_CS#1: JDIM1.121 U20.AK32
M_B_DQ0: JDIM1.36 U20.AP58
M_B_DQ1: JDIM1.34 U20.AR58
M_B_DQ2: JDIM1.22 U20.AM57
M_B_DQ3: JDIM1.24 U20.AK57
M_B_DQ4: JDIM1.21 U20.AL58
M_B_DQ5: JDIM1.23 U20.AK58
M_B_DQ6: JDIM1.33 U20.AR57
M_B_DQ7: JDIM1.35 U20.AN57
M_B_DQ8: JDIM1.41 U20.AP55
M_B_DQ9: JDIM1.39 U20.AR55
M_B_DQ10: JDIM1.53 U20.AM54
M_B_DQ11: JDIM1.51 U20.AK54
M_B_DQ12: JDIM1.40 U20.AL55
M_B_DQ13: JDIM1.42 U20.AK55
M_B_DQ14: JDIM1.52 U20.AR54
M_B_DQ15: JDIM1.50 U20.AN54
M_B_DQ16: JDIM1.4 U20.AK40
M_B_DQ17: JDIM1.6 U20.AK42
M_B_DQ18: JDIM1.17 U20.AM43
M_B_DQ19: JDIM1.18 U20.AM45
M_B_DQ20: JDIM1.16 U20.AK45
M_B_DQ21: JDIM1.15 U20.AK43
M_B_DQ22: JDIM1.5 U20.AM40
M_B_DQ23: JDIM1.7 U20.AM42
M_B_DQ24: JDIM1.68 U20.AM46
M_B_DQ25: JDIM1.70 U20.AK46
M_B_DQ26: JDIM1.57 U20.AM49
M_B_DQ27: JDIM1.59 U20.AK49
M_B_DQ28: JDIM1.69 U20.AM48
M_B_DQ29: JDIM1.67 U20.AK48
M_B_DQ30: JDIM1.56 U20.AM51
M_B_DQ31: JDIM1.58 U20.AK51
M_B_DQ32: JDIM1.129 U20.AM29
M_B_DQ33: JDIM1.131 U20.AK29
M_B_DQ34: JDIM1.143 U20.AL28
M_B_DQ35: JDIM1.140 U20.AK28
M_B_DQ36: JDIM1.130 U20.AR29
M_B_DQ37: JDIM1.132 U20.AN29
M_B_DQ38: JDIM1.141 U20.AR28
M_B_DQ39: JDIM1.142 U20.AP28
M_B_DQ40: JDIM1.147 U20.AN26
M_B_DQ41: JDIM1.146 U20.AR26
M_B_DQ42: JDIM1.148 U20.AR25
M_B_DQ43: JDIM1.149 U20.AP25
M_B_DQ44: JDIM1.158 U20.AK26
M_B_DQ45: JDIM1.160 U20.AM26
M_B_DQ46: JDIM1.159 U20.AK25
M_B_DQ47: JDIM1.157 U20.AL25
M_B_DQ48: JDIM1.177 U20.AR21
M_B_DQ49: JDIM1.164 U20.AR22
M_B_DQ50: JDIM1.174 U20.AL21
M_B_DQ51: JDIM1.165 U20.AM22
M_B_DQ52: JDIM1.163 U20.AN22
M_B_DQ53: JDIM1.176 U20.AP21
M_B_DQ54: JDIM1.175 U20.AK21
M_B_DQ55: JDIM1.166 U20.AK22
M_B_DQ56: JDIM1.180 U20.AN20
M_B_DQ57: JDIM1.182 U20.AR20
M_B_DQ58: JDIM1.194 U20.AK18
M_B_DQ59: JDIM1.191 U20.AL18
M_B_DQ60: JDIM1.193 U20.AK20
M_B_DQ61: JDIM1.192 U20.AM20
M_B_DQ62: JDIM1.183 U20.AR18
M_B_DQ63: JDIM1.181 U20.AP18
M_B_DQSN0: JDIM1.27 U20.AM58
M_B_DQSN1: JDIM1.45 U20.AM55
M_B_DQSN2: JDIM1.10 U20.AL43
M_B_DQSN3: JDIM1.62 U20.AL48
M_B_DQSN4: JDIM1.135 U20.AN28
M_B_DQSN5: JDIM1.152 U20.AN25
